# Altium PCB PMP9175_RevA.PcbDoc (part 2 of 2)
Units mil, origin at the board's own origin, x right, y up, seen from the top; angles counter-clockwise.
Board outline 3600 x 2200 mil, 4 copper layers (Top Layer, MidLayer1, MidLayer2, Bottom Layer), stack 73.2 mil thick; 114 components, 75 nets, 326 pads, 97 vias.
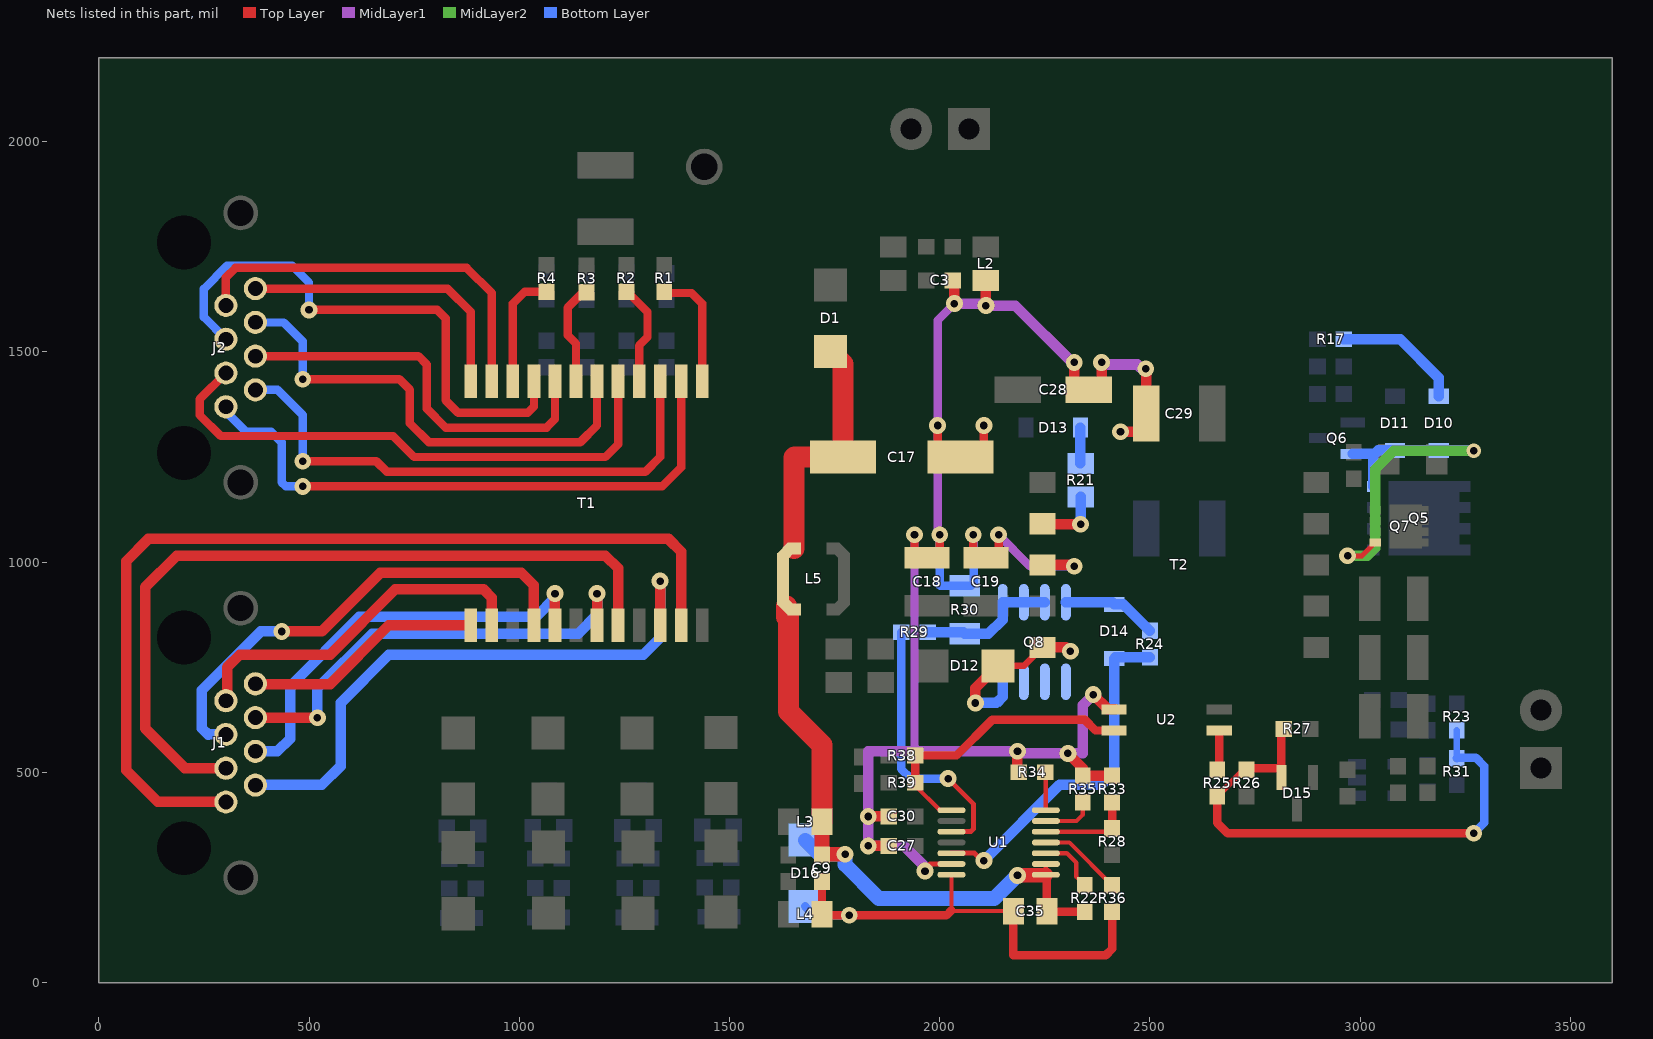
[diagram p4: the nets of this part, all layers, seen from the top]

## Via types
v1: diameter 40, hole 18, Top Layer to Bottom Layer, 93 vias
v2: diameter 35, hole 18, Top Layer to Bottom Layer, 4 vias

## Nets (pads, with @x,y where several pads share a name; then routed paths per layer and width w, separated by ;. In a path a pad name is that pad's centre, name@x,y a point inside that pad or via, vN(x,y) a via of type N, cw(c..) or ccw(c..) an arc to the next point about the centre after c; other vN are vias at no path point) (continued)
NetD10_1: D10.1 D11.1 Q5.4 Q6.2 Q7.4 | length 960.5
  Top Layer w12: v1(2970,1015) 3004.41,1015 Q7.4@3036.02,1046.61
  MidLayer2 w25: v1(2970,1015) 3017.06,1015 3036.02,1033.97 3036.02,1221.25 3079.77,1265 v2(3270,1265)
  Bottom Layer w25: Q6.2@2982.4,1257.6 3027.4,1257.6 3031.05,1253.95 ; Q5.4@3031.05,1179.98 3031.05,1253.95 ; v2(3270,1265) 3269.47,1265.53 D10.1@3187.09,1265.53 D11.1@3082.78,1265.53 3042.63,1265.53 3031.05,1253.95
NetD10_2: D10.2 R17.2 | length 307.2
  Bottom Layer w25: R17.2@2961.5,1530 3095,1530 3187.09,1437.91 D10.2@3187.09,1394.47
NetD12_2: D12.2 Q8.5 Q8.6 Q8.7 Q8.8 T2.1 | length 439.1
  Top Layer w15: D12.2@2138.66,753.23 2200.42,753.23 T2.1@2244.42,797.23
  Top Layer w25: v1(2085,665) 2085,700 D12.2@2138.23,753.23 ; T2.1@2244.42,797.23 2300,797.23 2313,784.23 2313.32,784.23 v1@2305,792.55
  Bottom Layer w25: v1(2085,665) 2135,665 2150,680 Q8.8@2150,715.51 ; v1@2305,792.55 2313.32,784.23 v1@2313,784.23
  other v1: 2310.71,788.13
NetD13_2: D13.2 R21.1 | length 84.5
  Bottom Layer w25: R21.1@2334.47,1235.53 D13.2@2334.47,1320
NetD14_1: D14.1 R24.1 U1.5 | length 833.8
  Top Layer w12: U1.5@2028.03,307.64 2082.64,307.64 2100.28,290 v1(2105,290)
  Bottom Layer w25: v1(2105,290) 2285,470 2385,470 2415,500 D14.1@2415,770.53 ; D14.1@2417.97,773.5 R24.1@2500,773.5
NetD14_2: D14.2 Q8.4 R24.2 | length 221.1
  Bottom Layer w25: Q8.4@2300,904.49 D14.2@2409.98,904.49 ; D14.2@2415,899.47 2437.03,899.47 R24.2@2500,836.5
NetD15_2: D15.2 R23.1 R25.2 R26.2 R27.2 R31.2 | length 1274.6
  Top Layer w15: R25.2@2659.92,443.03 R26.2@2722.91,506.02
  Top Layer w20: R25.2@2659.92,443.03 2659.92,380.08 2685,355 v1(3270,355) ; R26.2@2726.89,510 D15.2@2812.6,510 ; D15.2@2812.6,492.4 D15.2@2812.6,510 ; R27.2@2812.6,597.4 D15.2@2812.6,510
  Bottom Layer w15: R31.2@3229.92,533.43 R23.1@3229.92,600.43
  Bottom Layer w20: R31.2@3229.92,533.43 3231.5,535 3275,535 3295,515 3295,380 v1(3270,355)
NetJ1_1: J1.1 T1.23 | length 2295.4
  Top Layer w25: J1.1@302.44,429.45 301.89,430 140,430 65,505 65,1002.5 117.5,1055 1355,1055 1385,1025 T1.23@1385,850
NetJ1_2: J1.2 T1.22 | length 1435.5
  Top Layer w25: T1.22@1335,850 v1(1335,955)
  Bottom Layer w25: J1.2@372.52,469.61 372.91,470 530,470 575,515 575,665 690,780 1295,780 1335,820 v1(1335,955)
NetJ1_3: J1.3 T1.20 | length 1870.4
  Top Layer w25: J1.3@302.44,509.76 302.2,510 205,510 110,605 110,940 185,1015 1205,1015 1235,985 T1.20@1235,850
NetJ1_4: J1.4 T1.17 | length 1021.9
  Top Layer w25: T1.17@1085,850 1085,915 v1(1085,925)
  Bottom Layer w25: J1.4@372.52,549.92 424.92,549.92 455,580 455,705 620,870 1040,870 1085,915 v1(1085,925)
NetJ1_5: J1.5 T1.16 | length 1167.1
  Top Layer w25: v1(435,835) 530,835 670,975 1005,975 1035,945 T1.16@1035,850
  Bottom Layer w25: J1.5@302.44,590.08 260.08,590.08 260,590 245,605 245,695 385,835 v1(435,835)
NetJ1_6: J1.6 T1.19 | length 1080.1
  Top Layer w25: J1.6@372.52,630.24 372.76,630 v1(520,630) ; T1.19@1185,850 v1(1185,925)
  Bottom Layer w25: v1(520,630) 520,700 650,830 1140,830 1185,875 v1(1185,925)
NetJ1_7: J1.7 T1.14 | length 860.6
  Top Layer w25: J1.7@302.44,670.39 305,672.95 305,750 335,780 550,780 705,935 915,935 935,915 T1.14@935,850
NetJ1_8: J1.8 T1.13 | length 570.7
  Top Layer w25: J1.8@372.52,710.55 373.07,710 550,710 690,850 T1.13@885,850
NetJ2_1: J2.1 T1.2 | length 1437.3
  Top Layer w20: v1@495,1180 1340,1180 1385,1225 T1.2@1385,1430
  Bottom Layer w20: J2.1@302.44,1369.45 302.44,1357.56 350,1310 410,1310 435,1285 435,1190 445,1180 v1(485,1180)
NetJ2_2: J2.2 T1.3 | length 1302.3
  Top Layer w20: v1(485,1240) 660,1240 685,1215 1300,1215 1335,1250 T1.3@1335,1430
  Bottom Layer w20: J2.2@372.52,1409.61 424.61,1409.61 425,1410 485,1350 v1(485,1240)
NetJ2_3: J2.3 T1.5 | length 1324.5
  Top Layer w20: J2.3@302.44,1449.76 240,1387.32 240,1350 290,1300 700,1300 750,1250 1205,1250 1235,1280 T1.5@1235,1430
NetJ2_4: J2.4 T1.8 | length 942.7
  Top Layer w20: J2.4@372.52,1489.92 760.08,1489.92 780,1470 780,1365 825,1320 1065,1320 1085,1340 T1.8@1085,1430
NetJ2_5: J2.5 T1.9 | length 1312.9
  Top Layer w20: v1(500,1600) 805,1600 825,1580 825,1385 855,1355 1020,1355 1035,1370 T1.9@1035,1430
  Bottom Layer w20: J2.5@302.44,1530.08 250,1582.52 250,1650 305,1705 460,1705 500,1665 v1(500,1600)
NetJ2_6: J2.6 T1.6 | length 1151.8
  Top Layer w20: v1(485,1435) 715,1435 740,1410 740,1330 785,1285 1145,1285 1185,1325 T1.6@1185,1430
  Bottom Layer w20: J2.6@372.52,1570.24 372.76,1570 440,1570 485,1525 v1(485,1435)
NetJ2_7: J2.7 T1.11 | length 943.8
  Top Layer w20: J2.7@302.44,1610.39 302.44,1677.44 325,1700 875,1700 935,1640 T1.11@935,1430
NetJ2_8: J2.8 T1.12 | length 700.5
  Top Layer w20: J2.8@372.52,1650.55 373.07,1650 830,1650 885,1595 T1.12@885,1430
NetQ8_1: Q8.1 Q8.2 Q8.3 R29.2 R30.2 | length 329.9
  Bottom Layer w25: R29.2@1971.42,833.23 R30.2@2055.91,833.23 ; R30.2@2059.92,829.21 2115.95,829.21 2150,863.27 Q8.1@2150,904.49 Q8.2@2200,904.49 Q8.3@2250,904.49
NetR1_1: R1.1 T1.1 | length 286.8
  Top Layer w20: R1.1@1345,1643.5 1348.5,1640 1410,1640 1435,1615 T1.1@1435,1430
NetR2_1: R2.1 T1.4 | length 243.4
  Top Layer w20: R2.1@1255,1643.5 1256.5,1643.5 1305,1595 1305,1535 1285,1515 T1.4@1285,1430
NetR3_1: R3.1 T1.7 | length 243.7
  Top Layer w20: T1.7@1135,1430 1135,1520 1115,1540 1115,1605 1152.2,1642.2 R3.1@1160,1642.2
NetR4_1: R4.1 T1.10 | length 276.8
  Top Layer w20: T1.10@985,1430 985,1615 1013.5,1643.5 R4.1@1065,1643.5
NetR21_2: R21.2 T2.4 | length 154.4
  Top Layer w25: T2.4@2245.65,1090 v1(2335,1090)
  Bottom Layer w25: v1(2335,1090) R21.2@2335,1155
NetR22_1: R22.1 U1.10 | length 143.7
  Top Layer w10: U1.10@2252.44,307.64 2302.36,307.64 2325,285 2325,251.5 R22.1@2345,231.5
NetR25_1: R25.1 U2.1 | length 92.8
  Top Layer w20: R25.1@2659.92,506.02 R25.1@2662.95,509.06 ; R25.1@2664.92,511.02 U2.1@2664.92,599.53
NetR28_1: R28.1 R33.2 U1.12 | length 222.7
  Top Layer w10: U1.12@2252.44,358.82 2402.32,358.82 R28.1@2410,366.5
  Top Layer w20: R28.1@2410,366.5 R33.2@2410,428.5
NetR29_1: R29.1 U1.3 | length 645.6
  Top Layer w12: v1(2020,485) 2080,425 2080,365 2073.82,358.82 U1.3@2028.03,358.82
  Bottom Layer w20: R29.1@1908.43,833.23 1908.43,508.23 1931.65,485 v1(2020,485)
NetR34_2: R34.2 U1.14 | length 90.4
  Top Layer w10: R34.2@2251.5,500 2252.44,499.06 U1.14@2252.44,410
NetR35_2: R35.2 U1.13 | length 123.1
  Top Layer w10: U1.13@2252.44,384.41 2325.43,384.41 2340,398.98 R35.2@2340,428.5
NetR36_2: R36.2 U1.11 | length 199.7
  Top Layer w10: U1.11@2252.44,333.23 2308.27,333.23 R36.2@2410,231.5
NetR38_1: R38.1 R39.1 U1.1 U2.4 | length 703.4
  Top Layer w10: R39.1@1941.5,475 1941.5,468.5 2000,410 U1.1@2028.03,410
  Top Layer w20: R39.1@1941.5,475 R38.1@1941.5,540 2040,540 2125,625 2345,625 2370.47,599.53 U2.4@2416.89,599.53
PWRGND: C3.2 C17.2 C18.2 C19.2 C27.2 C28.2 C29.2 C30.2 L2.2 R30.1 R33.1 R34.1 R35.1 T2.3 U1.6 U2.3 | length 4793.5
  Top Layer w10: v1@1960,265 v1(1965,265) v1@1970,265
  Top Layer w12: v1@1960,265 1977.05,282.05 U1.6@2028.03,282.05
  Top Layer w20: v1(1940,1065) 1940,1010 1940.32,1010.32 C18.2@1969.92,1010.32 1999.68,1010.32 2000,1010 v1(2000,1065) ; v1(1995,1325) 1995,1315 1995,1250 C17.2@2049.76,1250 2105,1250 2105,1315 v1(2105,1325) ; v1(2080,1065) 2080,1010 2080.32,1010.32 C19.2@2109.92,1010.32 2139.68,1010.32 2140,1010 v1(2140,1065)
  Top Layer w25: v1(1830,325) C27.2@1878.5,325 ; v1(1830,395) C30.2@1878.5,395 ; C3.2@2031.5,1670 2035,1666.5 v1(2035,1615) ; v1(2110,1610) L2.2@2110,1670 ; v1(2185,550) 2185,503.5 R34.1@2188.5,500 ; T2.3@2244.42,993.23 v1@2316.77,993.23 ; v1(2305,545) 2340,510 R35.1@2340,491.5 R33.1@2410,491.5 ; v1(2320,1475) 2320,1470 2320,1410 C28.2@2354.65,1410 2385,1410 2385,1470 v1(2385,1475) ; v1(2365,685) 2400.47,649.53 U2.3@2416.89,649.53 ; v1(2430,1310) 2490,1310 2491.18,1311.18 C29.2@2491.18,1353.23 2491.18,1448.82 2490,1450 v1(2490,1460)
  MidLayer1 w20: v1(1940,1065) 1940,560 1950,550 ; v1(2000,1065) 1995,1070 1995,1315 1995,1575 v1(2035,1615) ; v1(2140,1065) 2215,990 v1(2320,990)
  MidLayer1 w25: v1@1960,265 v1(1965,265) ; v1@1970,265 v1(1965,265) ; v1(2035,1615) 2105,1615 v1(2110,1610) 2180,1610 2320,1470 v1(2320,1475) ; v1(2365,685) 2340,660 2340,545 2190,545 v1(2185,550) 1950,550 1830,550 v1(1830,395) v1(1830,325) 1915,325 1965,275 v1(1965,265) ; v1(2385,1475) 2385,1470 2470,1470 2490,1450 v1(2490,1460)
  Bottom Layer w20: v1(2000,1065) 2000,945 2001.61,943.39 R30.1@2059.92,943.39 2074.68,943.39 2080.67,949.37 2080.67,1064.33 v1(2080,1065)
VDD: C9.1 C17.1 C35.1 D1.1 D16.1 L3.2 L5.1 R22.2 U1.8 U1.9 | length 2164.6
  Top Layer w10: U1.8@2252.44,256.46 U1.9@2252.44,282.05
  Top Layer w20: U1.8@2252.44,256.46 2255,253.9 C35.1@2255,170 2256.5,168.5 R22.2@2345,168.5
  Top Layer w35: L3.2@1720,381.95 C9.1@1720,303.44 1721.56,305 v1(1775,305) ; v1(2185,255) 2250.98,255 U1.8@2252.44,256.46
  Top Layer w50: L5.1@1636,896 1636,869.5 1640,873.5 1640,645 1720,565 L3.2@1720,381.95 ; L5.1@1654,1032.5 1654,1249 1655,1250 1685,1250 ; 1690,1250 1685,1250 ; D1.1@1740,1501.26 1770.24,1471.02 C17.1@1770.24,1250 1685,1250
  Bottom Layer w35: D16.1@1680,338.74 1713.74,305 v1(1775,305) 1775,280 1855,200 2130,200 v1(2185,255)
VSS: C9.2 C35.2 D16.2 L4.2 R36.1 U1.7 | length 1173.1
  Top Layer w10: U1.7@2028.03,256.46 2028.03,171.97 2030,170 C35.2@2175,170
  Top Layer w20: C9.2@1720,240.45 L4.2@1720,161.95 1721.95,160 v1(1785,160) 2016.06,160 2028.03,171.97 ; C35.2@2175,170 2175,65 2395,65 2410,80 R36.1@2410,168.5
  Bottom Layer w20: D16.2@1680,181.26 1701.26,160 v1(1785,160)
pads on no net: J1.MH1 J1.MH2 J1.MH3 J1.MH4 J2.MH1 J2.MH2 J2.MH3 J2.MH4 T2.5 T2.8 T2.9 U3.1 U3.2

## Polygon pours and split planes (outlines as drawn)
PWRGND on MidLayer2 "MidLayer2-No Net" (solid, remove dead copper, pour order 67): 1600,1700 2530,1700 2530,270 2220,270 2220,450 2060,450 2060,280 1802.43,280 1796.3,286.14 1796.3,535 1795,535 1600,730 1600,1700
GND on MidLayer2 "MidLayer2-No Net 1" (solid, remove dead copper, pour order 66): 2610,2150 3550,2150 3550,50 2610,50
EARTH on MidLayer2 "MidLayer2-EARTH" (solid, remove dead copper, pour order 76): 1500,800 1499.7,799.7 650,799.7 650,100 100,100 100,2100 1500,2100 1500,800
GND on MidLayer1 "MidLayer1-GND" (solid, remove dead copper, pour order 69): 2610,1380 2610,2150 3550,2150 3550,50 2610,50
PWRGND on MidLayer1 "MidLayer1-PWRGND" (solid, remove dead copper, pour order 68): 2530,1360 2530,1700 1660,1700 1660,600 1660,500 1800,500 1800,280 2060,280 2060,450 2220,450 2220,270 2530,270
EARTH on MidLayer1 "MidLayer1-EARTH" (solid, remove dead copper, pour order 75): 650,100 650,800 1500,800 1500,2100 100,2100 100,100
GND on Bottom Layer "Bottom Layer-GND" (solid, remove dead copper, pour order 72): 2610,2150 3550,2150 3550,50 2610,50
NetC21_1 on Bottom Layer "Bottom Layer-NetC21_1" (solid, remove dead copper, pour order 71): 3070,970 3070,1195 3310,1195 3310,970
NetC26_2 on Bottom Layer "Bottom Layer-NetC26_2" (solid, remove dead copper, pour order 62): 3045,1014.13 3045,1140 3014.25,1140 3012.8,1138.54 2986.38,1164.96 2805.04,1164.96 2805,1164.92 2805,1060 2994.92,1060 2994.96,1060.04 3012.8,1042.2 3012.8,1014.13
NetD12_2 on Bottom Layer "Bottom Layer-NetD12_2" (solid, remove dead copper, pour order 57): 2065,645 2320,645 2320,820 2165,820 2065,720 2065,710
NetD12_2 on Bottom Layer "Bottom Layer-No Net 1" (solid, remove dead copper, pour order 56): 2190,705 2190,860 2325,860 2325,705
PWRGND on Bottom Layer "Bottom Layer-PWRGND" (solid, pour order 64): 1600,1700 2530,1700 2530,270 2220,270 2220,450 2065,450 2060,445 2053.62,438.62 2053.62,277.22 2050.85,280 1860,280 1847.79,280 1815.29,312.5 1815,312.79 1815,526.67 1803.33,526.67 1600,730 1600,1700
EARTH on Bottom Layer "Bottom Layer-EARTH" (solid, remove dead copper, pour order 74): 100,2100 1500,2100 1500,800 650,800 650,100 100,100
NetC21_1 on Top Layer "Top Layer-NetC21_1" (solid, remove dead copper, pour order 43): 3144.59,1300 3144.59,1175.41 3145,1175 3070,1175 3070,1015 3110,975 3110,545 3070,545 3070,495 3310,495 3310,595 3550,595 3550,725 3310,725 3310,1175 3230,1175 3230,1300
NetC4_1 on Top Layer "Top Layer-NetC4_1" (solid, remove dead copper, pour order 54): 1370,265 1540,265 1540,490 1370,490
NetC5_1 on Top Layer "Top Layer-NetC5_1" (solid, remove dead copper, pour order 53): 1340,265 1338.5,266.5 1338.5,490 1170,490 1170,265
NetC6_1 on Top Layer "Top Layer-NetC6_1" (solid, remove dead copper, pour order 52): 1130,490 1130,265 960,265 960,490
NetC7_1 on Top Layer "Top Layer-NetC7_1" (solid, remove dead copper, pour order 49): 913.5,490 915,488.5 915,265 735,265 735,490
NetC8_2 on Top Layer "Top Layer-NetC8_2" (solid, remove dead copper, pour order 47): 785,215 1550,215 1550,127.28 1550,125 785,125
NetC8_1 on Top Layer "Top Layer-NetC8_1" (solid, remove dead copper, pour order 45): 786.1,550 785,551.1 785,700 1550,700 1550,551.1 1548.9,550
GND on Top Layer "Top Layer-GND" (solid, remove dead copper, pour order 70): 2610,2150 3550,2150 3550,50 2610,50
NetC26_2 on Top Layer "Top Layer-NetC26_2" (solid, remove dead copper, pour order 63): 3045.28,1065.51 2805.51,1065.51 2805,1065 2805,1165 2845,1165 2855,1155 2855,1135 2930,1135 2960,1165 2960,1220 3010,1220 3010,1160 3045,1160
NetC15_2 on Top Layer "Top Layer-No Net 3" (solid, remove dead copper, pour order 48): 1725,765 1725,1050 1830,1050 1830,945 2280,945 2280,850 1895,850 1895,765
NetC2_2 on Top Layer "Top Layer-No Net 4" (solid, remove dead copper, pour order 51): 2010,1720 2010,2080 2150,2080 2150,1720
NetD12_2 on Top Layer "Top Layer-No Net 5" (solid, pour order 55): 2330.32,825.27 2100.27,825.27 2100,825 2100,710 2330,710
VSS on Top Layer "Top Layer-VSS" (solid, remove dead copper, pour order 44): 2210,50 1690,50 1690,260 1900,260 1900,200 2210,200
VDD on Top Layer "Top Layer-VDD" (solid, remove dead copper, pour order 46): 1600,1540 1600,500 1640,500 1690,450 1690,280 1800,280 1800,530 1670,660 1670,1100 1850,1100 1850,1540
NetC15_2 on Top Layer "Top Layer-No Net 6" (solid, pour order 58): 2270,945 2345,945 2360,960 2449.84,960 2449.84,816.46 2448.39,815 2390,815 2385,815 2350,850 2270.79,850
VDD on Top Layer "Top Layer-No Net 7" (solid, pour order 59): 2230,130 2230,225 2165,225 2165,285 2285,285 2295,285 2300,280 2300,190 2363.7,190 2365,188.7 2365,130
NetC2_1 on Top Layer "Top Layer-No Net 8" (solid, pour order 60): 1990,1721.46 1826.46,1721.46 1825,1720 1825,2080 1990,2080
AUX on Top Layer "Top Layer-No Net 9" (solid, pour order 61): 1990,1700 1650,1700 1650,1600 1990,1600
PWRGND on Top Layer "Top Layer-PWRGND" (solid, remove dead copper, pour order 65): 2530,1700 2530,270 2220,270 2220,450 2060,450 2060,280 1802.43,280 1795,287.43 1795,550 1780,550 1600,730 1600,1550 1600,1700
NetC26_1 on Top Layer "Top Layer-NetC26_1" (solid, remove dead copper, pour order 42): 2960,1240 2960,1300 3110,1300 3110,1195 3040,1195 3040,1240
EARTH on Top Layer "Top Layer-EARTH" (solid, remove dead copper, pour order 73): 100,2100 1500,2100 1500,800 650,800 650,100 100,100 100,2100

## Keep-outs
Keep-Out Layer:
  lines w10: -5,0 ccw(c0,0) 0,-5 ; -5,0 ccw(c0,0) 0,-5 ; -5,0 -5,2200 ; -5,2200 cw(c0,2200) 0,2205 ; -5,2200 cw(c0,2200) 0,2205 ; 0,-5 3600,-5 ; 0,2205 3600,2205 ; 3600,-5 ccw(c3600,0) 3605,0 ; 3600,-5 ccw(c3600,0) 3605,0 ; 3600,2205 cw(c3600,2200) 3605,2200 ; 3600,2205 cw(c3600,2200) 3605,2200 ; 3605,0 3605,2200
  text ".Layer_Name" at 577,-858.49 h60

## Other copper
Top Layer:
  rectangle net PWRGND: 1945,245 1984.72,290
  text ".Layer_Name" at 577,-858.49 h60
MidLayer1:
  rectangle net PWRGND: 1940,245 2060,288.61
MidLayer2:
  rectangle net PWRGND: 1940,245 2060,288.61
Bottom Layer:
  rectangle net PWRGND: 1940,245 2053.62,286.87
  rectangle net PWRGND: 1950,245 1984.72,290
  text ".Layer_Name" at 577,-858.49 h60

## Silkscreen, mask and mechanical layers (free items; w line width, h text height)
Top Overlay:
  rectangle: 2750,1650 3500,1750
  text "2013" at 2525,1890 h35
  text "PMP9175 REV A" at 2755,1800 h60
  text ".Layer_Name" at 577,-858.49 h60
Bottom Overlay:
  text ".Layer_Name" at 577,-858.49 h60
Top Paste:
  text ".Layer_Name" at 577,-858.49 h60
Bottom Paste:
  text ".Layer_Name" at 577,-858.49 h60
Top Solder:
  text ".Layer_Name" at 577,-858.49 h60
  text ".Layer_Name" at 577,-858.49 h60
Bottom Solder:
  text ".Layer_Name" at 577,-858.49 h60
Drill Guide:
  text ".Layer_Name" at 577,-858.49 h60
M1 Board Outline:
  the board outline again, w10
  text ".Layer_Name" at 577,-858.49 h60
M2 Board Dimensions:
  rectangle: -0.5,-285.5 124.5,-160.5
  rectangle: 124.5,-410.5 499.5,-285.5
  lines w7: -0.5,-285.5 999.5,-285.5 ; 124.5,-410.5 124.5,-160.5 ; 249.5,-410.5 249.5,-160.5 ; 499.5,-410.5 499.5,-160.5 ; 749.5,-410.5 749.5,-160.5 ; -0.5,-410.5 999.5,-410.5 999.5,-160.5 -0.5,-160.5 -0.5,-410.5
  lines w10: -0.5,-475.5 -0.5,-455.5 ; 59.5,-485.5 -0.5,-465.5 ; 59.5,-445.5 -0.5,-465.5 ; 223.58,-465.5 -0.5,-465.5 ; 775.42,-465.5 999.5,-465.5 ; 939.5,-485.5 999.5,-465.5 ; 939.5,-445.5 999.5,-465.5 ; 999.5,-475.5 999.5,-455.5
  text "1000 (mil)" at 233.58,-501.49 h60
  text ".Layer_Name" at 577,-858.49 h60
M3 3D STEP Top:
  text ".Layer_Name" at 577,-858.49 h60
M4 3D STEP Bottom:
  text ".Layer_Name" at 577,-858.49 h60
M5 Assembly Top:
  lines w10: -292,-930.17 6308,-930.17 ; -292,-726.83 6310,-726.83 ; -292,-523.5 -292,-1133.5 3713,-1133.5 6310,-1133.5 6310,-523.5 -291.5,-523.5 -291.5,-1133.5 1284,-1133.5 ; 2173,-1133.5 2173,-523.5 ; 3440,-726.83 3440,-523.5 ; 4280,-726.83 4280,-523.5 ; 4902,-1140 4902,-937.17
  text "COMPONENTS MARKED 'DNP' SHOULD NOT BE POPULATED." at 1153.5,-318.5 h60
  text "ASSEMBLY VARIANT:" at 1153,-434 h60
  text ".VariantName" at 2189,-434 h60
  text "PCB VIEWED FROM TOP SIDE" at -228.5,-655.67 h60
  text "BOARD #:" at 2248,-655.67 h60
  text ".PRJ_Number" at 2793.5,-655.67 h60
  text "REV:" at 3638,-655.67 h60
  text ".PCB_Rev" at 3929.5,-655.67 h60
  text "SVN REV:" at 4476,-655.67 h60
  text ".VersionControl_RevNumber" at 4982,-655.67 h60
  text "IGNORE ->" at -228.5,-858.49 h60
  text "PLOT NAME =" at -228.5,-1064.34 h60
  text ".plot_File_Name" at 577,-1064.34 h60
  text "GENERATED    :" at 2250,-1064.34 h60
  text ".Print_Date" at 3119.5,-1064.34 h60
  text ".Print_Time" at 3848.5,-1064.34 h60
  text "TEXAS INSTRUMENTS" at 5113,-1064.34 h60
M6 Assembly Bottom:
  lines w10: -292.5,-727.33 6309.5,-727.33 ; -290.5,-930.67 6309.5,-930.67 ; 1115.5,-1140.5 1115.5,-937.67 ; 1737.5,-727.33 1737.5,-524 ; 2577.5,-727.33 2577.5,-524 ; 3844.5,-1134 3844.5,-524 ; 4733.5,-1134 6309,-1134 6309,-524 -292.5,-524 -292.5,-1134 2304.5,-1134 6309.5,-1134 6309.5,-524
  text "COMPONENTS MARKED 'DNP' SHOULD NOT BE POPULATED." at 6102,-318 h60
  text ".VariantName" at 5058,-434 h60
  text "ASSEMBLY VARIANT:" at 6097,-434 h60
  text ".VersionControl_RevNumber" at 1035.5,-656.17 h60
  text "SVN REV:" at 1541.5,-656.17 h60
  text ".PCB_Rev" at 2088,-656.17 h60
  text "REV:" at 2379.5,-656.17 h60
  text ".PRJ_Number" at 3224,-656.17 h60
  text "BOARD #:" at 3769.5,-656.17 h60
  text "PCB VIEWED FROM BOTTOM SIDE" at 6246,-656.17 h60
  text "IGNORE ->" at 2547.85,-858.49 h60
  text "TEXAS INSTRUMENTS" at 904.5,-1064.84 h60
  text ".Print_Time" at 2169,-1064.84 h60
  text ".Print_Date" at 2898,-1064.84 h60
  text "GENERATED    :" at 3767.5,-1064.84 h60
  text ".plot_File_Name" at 5440.5,-1064.84 h60
  text "PLOT NAME =" at 6246,-1064.84 h60
M9 Title Sheet:
  drawing of 57 lines, arcs and shapes, not listed
  text "1" at 739.84,8036.5 h70
  text "2" at 3235.5,8036.5 h70
  text "3" at 5724.84,8036.5 h70
  text "4" at 8231.51,8036.5 h70
  text "5" at 10730.5,8036.5 h70
  text "6" at 13235.5,8036.5 h70
  text "A" at -416.5,6893.5 h70
  text "A" at 14383.5,6893.5 h70
  text "B" at -416.5,4513.5 h70
  text "B" at 14383.5,4513.5 h70
  text "C" at -416.5,2138.5 h70
  text "C" at 14383.5,2138.5 h70
  text "PROJECT TITLE:" at 11343.5,277.5 h45
  text ".PRJ_Title" at 11393.5,144.17 h70
  text "DESIGNED FOR:" at 11343.5,-23.5 h45
  text ".PRJ_Customer" at 11393.5,-163.5 h70
  text "D" at -416.5,-231.5 h70
  text "D" at 14383.5,-231.5 h70
  text "FILE NAME:" at 11343.5,-323.5 h45
  text ".PCB_File_Name_No_Path" at 11393.5,-443.5 h70
  text "Texas Instruments (TI) and/or its licensors do not warrant the accuracy or completeness of this specification" at 6374,-605.34 h45
  text "ENGINEER:" at 11343.5,-613.5 h45
  text "LAYOUT BY:" at 12848.5,-613.5 h45
  text "or any information contained therein. TI and/or its licensors do not warrant that this design will meet" at 6329.01,-718 h45
  text ".PRJ_Engineer" at 11393.5,-768.49 h70
  text ".PCB_Layout" at 12899,-768.49 h70
  text "the specifications, will be suitable for your application or fit for any particular purpose, or will operate in" at 6329.01,-830.67 h45
  text ".Layer_Name" at 577,-858.49 h60
  text "ALTIUM DESIGNER VERSION:" at 12848.5,-923.5 h45
  text "an implementation. TI and/or its licensors do not warrant that the design is production worthy. You should" at 6329.01,-943.33 h45
  text "completely validate and test your design implementation to confirm the system functionality for your application." at 6374,-1056 h45
  text ".print_Scale" at 11393.5,-1056.83 h70
  text ".Application_BuildNumber" at 12899,-1056.83 h70
  text "1" at 739.84,-1263.5 h70
  text "2" at 3235.5,-1263.5 h70
  text "3" at 5724.84,-1263.5 h70
  text "4" at 8231.51,-1263.5 h70
  text "5" at 10730.5,-1263.5 h70
  text "6" at 13235.5,-1263.5 h70
M10 Fab Notes:
  drawing of 212 lines, arcs and shapes, not listed
  text "DESIGN INFORMATION" at 12381.02,6810 h60
  text "(REFER ALSO ARRAY/PANEL PROFILING INFORMATION)" at 12019.46,6648.29 h60
  text "BOARD SIZE" at 11333.46,6644 h60
  text "2200MIL" at 11795.78,6516.18 h60
  text "X" at 12301.46,6516.18 h60
  text "3600MIL" at 12532.78,6516.18 h60
  text "Number of Layers :" at 11736.46,6319 h60
  text "4" at 12831.27,6309 h60
  text "MIN. TRACK WIDTH:" at 11736.46,6180 h60
  text "8" at 12832.7,6180 h60
  text "MIL" at 12987.46,6180 h60
  text "MIN. CLEARANCE:" at 11736.46,6048 h60
  text "8" at 12832.7,6048 h60
  text "MIL" at 12987.46,6048 h60
  text "MIN. VIA PAD SIZE:" at 11736.46,5916 h60
  text "24" at 12802.71,5916 h60
  text "MIL" at 12987.46,5916 h60
  text "0.05mm (2MIL)" at 12431.46,5774.29 h60
  text "MINIMUM ANNULAR RING" at 11407.23,5770 h60
  text "EXTERNAL" at 13139.46,5770 h60
  text "PER" at 11607.23,5652 h60
  text "IPC-D-275 CLASS 2 LEVEL C" at 11827.23,5652 h60
  text "MIL, HOLES" at 13315.46,5539.71 h60
  text "+/-" at 12923,5539 h60
  text "+/-" at 13777,5539 h60
  text "REGISTRATION TOLERANCES:" at 11407.23,5534 h60
  text "METAL" at 12607,5534 h60
  text "5" at 13183.2,5534 h60
  text "3" at 14016.2,5534 h60
  text "MIL" at 14132.46,5534 h60
  text "MATERIAL:" at 11332.46,5324.54 h60
  text "X" at 11610,5185 h60
  text "FR-4 High Tg" at 12318.9,5184.21 h60
  text "FR-408" at 11753.46,5175.64 h60
  text "OTHER" at 13241.46,5175.64 h60
  text "62 MIL (1.6mm) +/-10%" at 12073.56,5012.92 h60
  text "THICKNESS:" at 11407.23,5008.64 h60
  text "X" at 11945.4,5008.64 h60
  text "OTHER" at 13358.46,5008.64 h60
  text "TOLERANCE:" at 11407.23,4850.64 h60
  text "X" at 12246.53,4850.64 h60
  text "ANSI IPC-6012 TYPE 3 CLASS 2" at 12433.48,4850.64 h60
  text "OTHER +/-" at 12433.46,4694.64 h60
  text "BOW & TWIST:" at 11407.23,4537.64 h60
  text "X" at 12246.53,4537.64 h60
  text "ANSI IPC-6012 TYPE 3 CLASS 2" at 12433.48,4537.64 h60
  text "OTHER +/-" at 12433.46,4379.13 h60
  text "COPPER THICKNESS (FINISHED):" at 11332.46,4243.64 h60
  text "1.4MIL (1oz)" at 12212.46,4090.92 h60
  text "2MIL (1.4oz)" at 12979.46,4090.92 h60
  text "2.8MIL (2oz)" at 13706.46,4090.92 h60
  text "X" at 13590,4090 h60
  text "OUTER:" at 11689.46,4086.64 h60
  text "1.4MIL (1oz)" at 12212.46,3933.92 h60
  text "2.8MIL (2oz)" at 12979.46,3933.92 h60
  text "N/A" at 13706,3934.29 h60
  text "INNER SIGNAL:" at 11400.38,3929.64 h60
  text "X" at 12850,3930 h60
  text "DRILLING:" at 11332.46,3790.64 h60
  text "REFERENCE:" at 11407.23,3673.64 h60
  text "X" at 12055.46,3673.64 h60
  text "AS SHOWN" at 12242.46,3673.64 h60
  text "X" at 12956.46,3673.64 h60
  text "NC_DRILL FILES" at 13093.46,3673.64 h60
  text "PTH MIN COPPER THICKNESS:" at 11407.23,3515.64 h60
  text "X" at 12757.46,3515.64 h60
  text "1MIL" at 12894.46,3515.64 h60
  text "OTHER" at 13391.46,3515.64 h60
  text "BOARD FINISH:" at 11332.46,3356.64 h60
  text "SILKSCREEN:" at 11487.68,3238.64 h60
  text "X" at 12436.46,3238.64 h60
  text "TOP" at 12562.46,3238.64 h60
  text "X" at 12946.46,3238.64 h60
  text "BOTTOM" at 13073.46,3238.64 h60
  text "SILKSCREEN COLOR:" at 11487.68,3071.64 h60
  text "X" at 12435.42,3071.64 h60
  text "WHITE" at 12562.46,3071.64 h60
  text "OTHER" at 13073.46,3071.64 h60
  text "SOLDER RESIST COLOR:" at 11487.68,2901.64 h60
  text "X" at 12055.42,2742.44 h60
  text "GREEN" at 12182.46,2742.44 h60
  text "BLUE" at 12773.46,2742.44 h60
  text "OTHER" at 13311.46,2742.44 h60
  text "IMMERSION GOLD (ENIG)" at 12393.46,2553.92 h60
  text "ENEPIG" at 13731,2550.64 h60
  text "SURFACE FINISH:" at 11332.46,2549.64 h60
  text "X" at 11500,2405 h60
  text "IMM. TIN/SILVER OR EQUIV" at 11662,2392.64 h60
  text "OTHER" at 13093.46,2392.64 h60
  text "X" at 12205,2215 h60
  text "ARRAY/PANEL:" at 11332.46,2213.64 h60
  text "CUT AND TRIM PER MECH LAYER 1" at 12393.46,2209.35 h60
  text "N.C. ROUTE" at 12393.46,2057.64 h60
  text "V. SCORE" at 13259.46,2057.64 h60
  text "CERTIFICATION:" at 11332.46,1920.64 h60
  text "MATERIALS AND WORKMANSHIP FOR ALL PCBS" at 12057.46,1920.64 h60
  text "TO MEET OR EXCEED THE REQUIREMENTS OF:" at 12057.46,1822.64 h60
  text "X" at 11683.96,1686.13 h60
  text "ANSI IPC-A-600F CLASS ->" at 11822.96,1686.13 h60
  text "X" at 13462.02,1686.13 h60
  text "2" at 13580.96,1686.14 h60
  text "1" at 13265.96,1684.64 h60
  text "3" at 13934.96,1684.64 h60
  text "X" at 11686.02,1526.64 h60
  text "UL 94V-0" at 11822.96,1526.64 h60
  text "X" at 12498.02,1526.64 h60
  text "RoHS" at 12634.96,1526.64 h60
  text "OTHER" at 13279.36,1526.64 h60
  text "PER ORDER" at 13676.42,1526.64 h60
  text "ADDITIONAL REQUIREMENTS:" at 11332.46,1385.64 h60
  text "MICROSECTION:" at 11407.23,1270.64 h60
  text "YES" at 12312.96,1270.64 h60
  text "X" at 12590,1115 h60
  text "REQUIRED" at 13174.46,1114.49 h60
  text "BARE BOARD ELEC. TEST:" at 11407.23,1111.64 h60
  text "NONE" at 12712.96,1111.64 h60
  text "PER ORDER" at 13766.46,1111.64 h60
  text "MANUFACTURER'S UL:" at 11407.23,954.64 h60
  text "RAIL" at 12572.96,950.35 h60
  text "METAL" at 13064.77,950.35 h60
  text "X" at 13440,950 h60
  text "SILK" at 13576.46,950.35 h60
  text ".Layer_Name" at 577,-858.49 h60
M11 Gerber Information:
  lines w10: -292,-930.17 6308,-930.17 ; -292,-726.83 6310,-726.83 ; -292,-523.5 -292,-1133.5 3713,-1133.5 6310,-1133.5 6310,-523.5 -291.5,-523.5 -291.5,-1133.5 1284,-1133.5 ; 2173,-1133.5 2173,-523.5 ; 3440,-726.83 3440,-523.5 ; 4280,-726.83 4280,-523.5 ; 4902,-1140 4902,-937.17
  text "ALL ARTWORK VIEWED FROM TOP SIDE" at -228.5,-655.67 h60
  text "BOARD #:" at 2248,-655.67 h60
  text ".PRJ_Number" at 2793.5,-655.67 h60
  text "REV:" at 3638,-655.67 h60
  text ".PCB_Rev" at 3929.5,-655.67 h60
  text "SVN REV:" at 4476,-655.67 h60
  text ".VersionControl_RevNumber" at 4982,-655.67 h60
  text "LAYER NAME =" at -228.5,-858.49 h60
  text "PLOT NAME =" at -228.5,-1064.34 h60
  text ".plot_File_Name" at 577,-1064.34 h60
  text "GENERATED    :" at 2250,-1064.34 h60
  text ".Print_Date" at 3119.5,-1064.34 h60
  text ".Print_Time" at 3848.5,-1064.34 h60
  text "TEXAS INSTRUMENTS" at 5113,-1064.34 h60
M12 Stackup:
  lines w6: 11365,7680.5 14205,7680.5 ; 11365,7789 14205,7789 ; 11305,6985 ccw(c11340,6985) 11340,6950 14230,6950 ccw(c14230,6985) 14265,6985 14265,7885 ccw(c14230,7885) 14230,7920 11340,7920 ccw(c11340,7885) 11305,7885 11305,6985
  text "Layer Stack Up Detail for: PMP9175_RevA.PcbDoc" at 11365,7817.5 h50
  text "Layer" at 11365,7748.5 h25
  text "Gerber" at 12358.47,7748.5 h25
  text "Copper" at 13012.92,7748.5 h25
  text "Dielectric" at 13708.19,7748.5 h25
  text "Name" at 11365,7698.5 h25
  text "Document" at 12358.47,7698.5 h25
  text "Thickness" at 13012.92,7698.5 h25
  text "Material" at 13708.19,7698.5 h25
  text "Top Solder Mask" at 11365,7626.98 h35
  text "(.GTS)" at 12358.47,7626.98 h35
  text "Solder Resist" at 13708.19,7626.98 h35
  text "Top Layer" at 11365,7525.94 h35
  text "(.GTL)" at 12358.47,7525.94 h35
  text "2.8mil" at 13012.92,7525.94 h35
  text "FR-4" at 13708.19,7475.42 h35
  text "MidLayer1" at 11365,7424.9 h35
  text "(.G1)" at 12358.47,7424.9 h35
  text "2.8mil" at 13012.92,7424.9 h35
  text "FR-4" at 13708.19,7374.38 h35
  text "MidLayer2" at 11365,7323.85 h35
  text "(.G2)" at 12358.47,7323.85 h35
  text "2.8mil" at 13012.92,7323.85 h35
  text "FR-4" at 13708.19,7273.33 h35
  text "Bottom Layer" at 11365,7222.81 h35
  text "(.GBL)" at 12358.47,7222.81 h35
  text "2.8mil" at 13012.92,7222.81 h35
  text "Bottom Solder Mask" at 11365,7121.77 h35
  text "(.GBS)" at 12358.47,7121.77 h35
  text "Solder Resist" at 13708.19,7121.77 h35
  text ".Layer_Name" at 577,-858.49 h60
M13 Component Bodies Top:
  text ".Layer_Name" at 577,-858.49 h60
M14 Component Bodies Bottom:
  text ".Layer_Name" at 577,-858.49 h60
M15 Courtyards Top:
  text ".Layer_Name" at 577,-858.49 h60
M16 Courtyards Bottom:
  text ".Layer_Name" at 577,-858.49 h60
Drill Drawing:
  text ".legend" at 3992.5,505.5 h60
  text "Drill Table" at 4017.5,320.5 h60
  text ".Layer_Name" at 577,-858.49 h60

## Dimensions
0,0 to 0,2200 on M2 Board Dimensions
0,0 to 3600,0 on M2 Board Dimensions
